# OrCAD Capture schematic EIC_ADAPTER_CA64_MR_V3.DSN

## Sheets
1 PAGE1-BIS: size A3; title: EIC-Adapter_Carrier-ALCOR 64; rev: 3; note: Connections
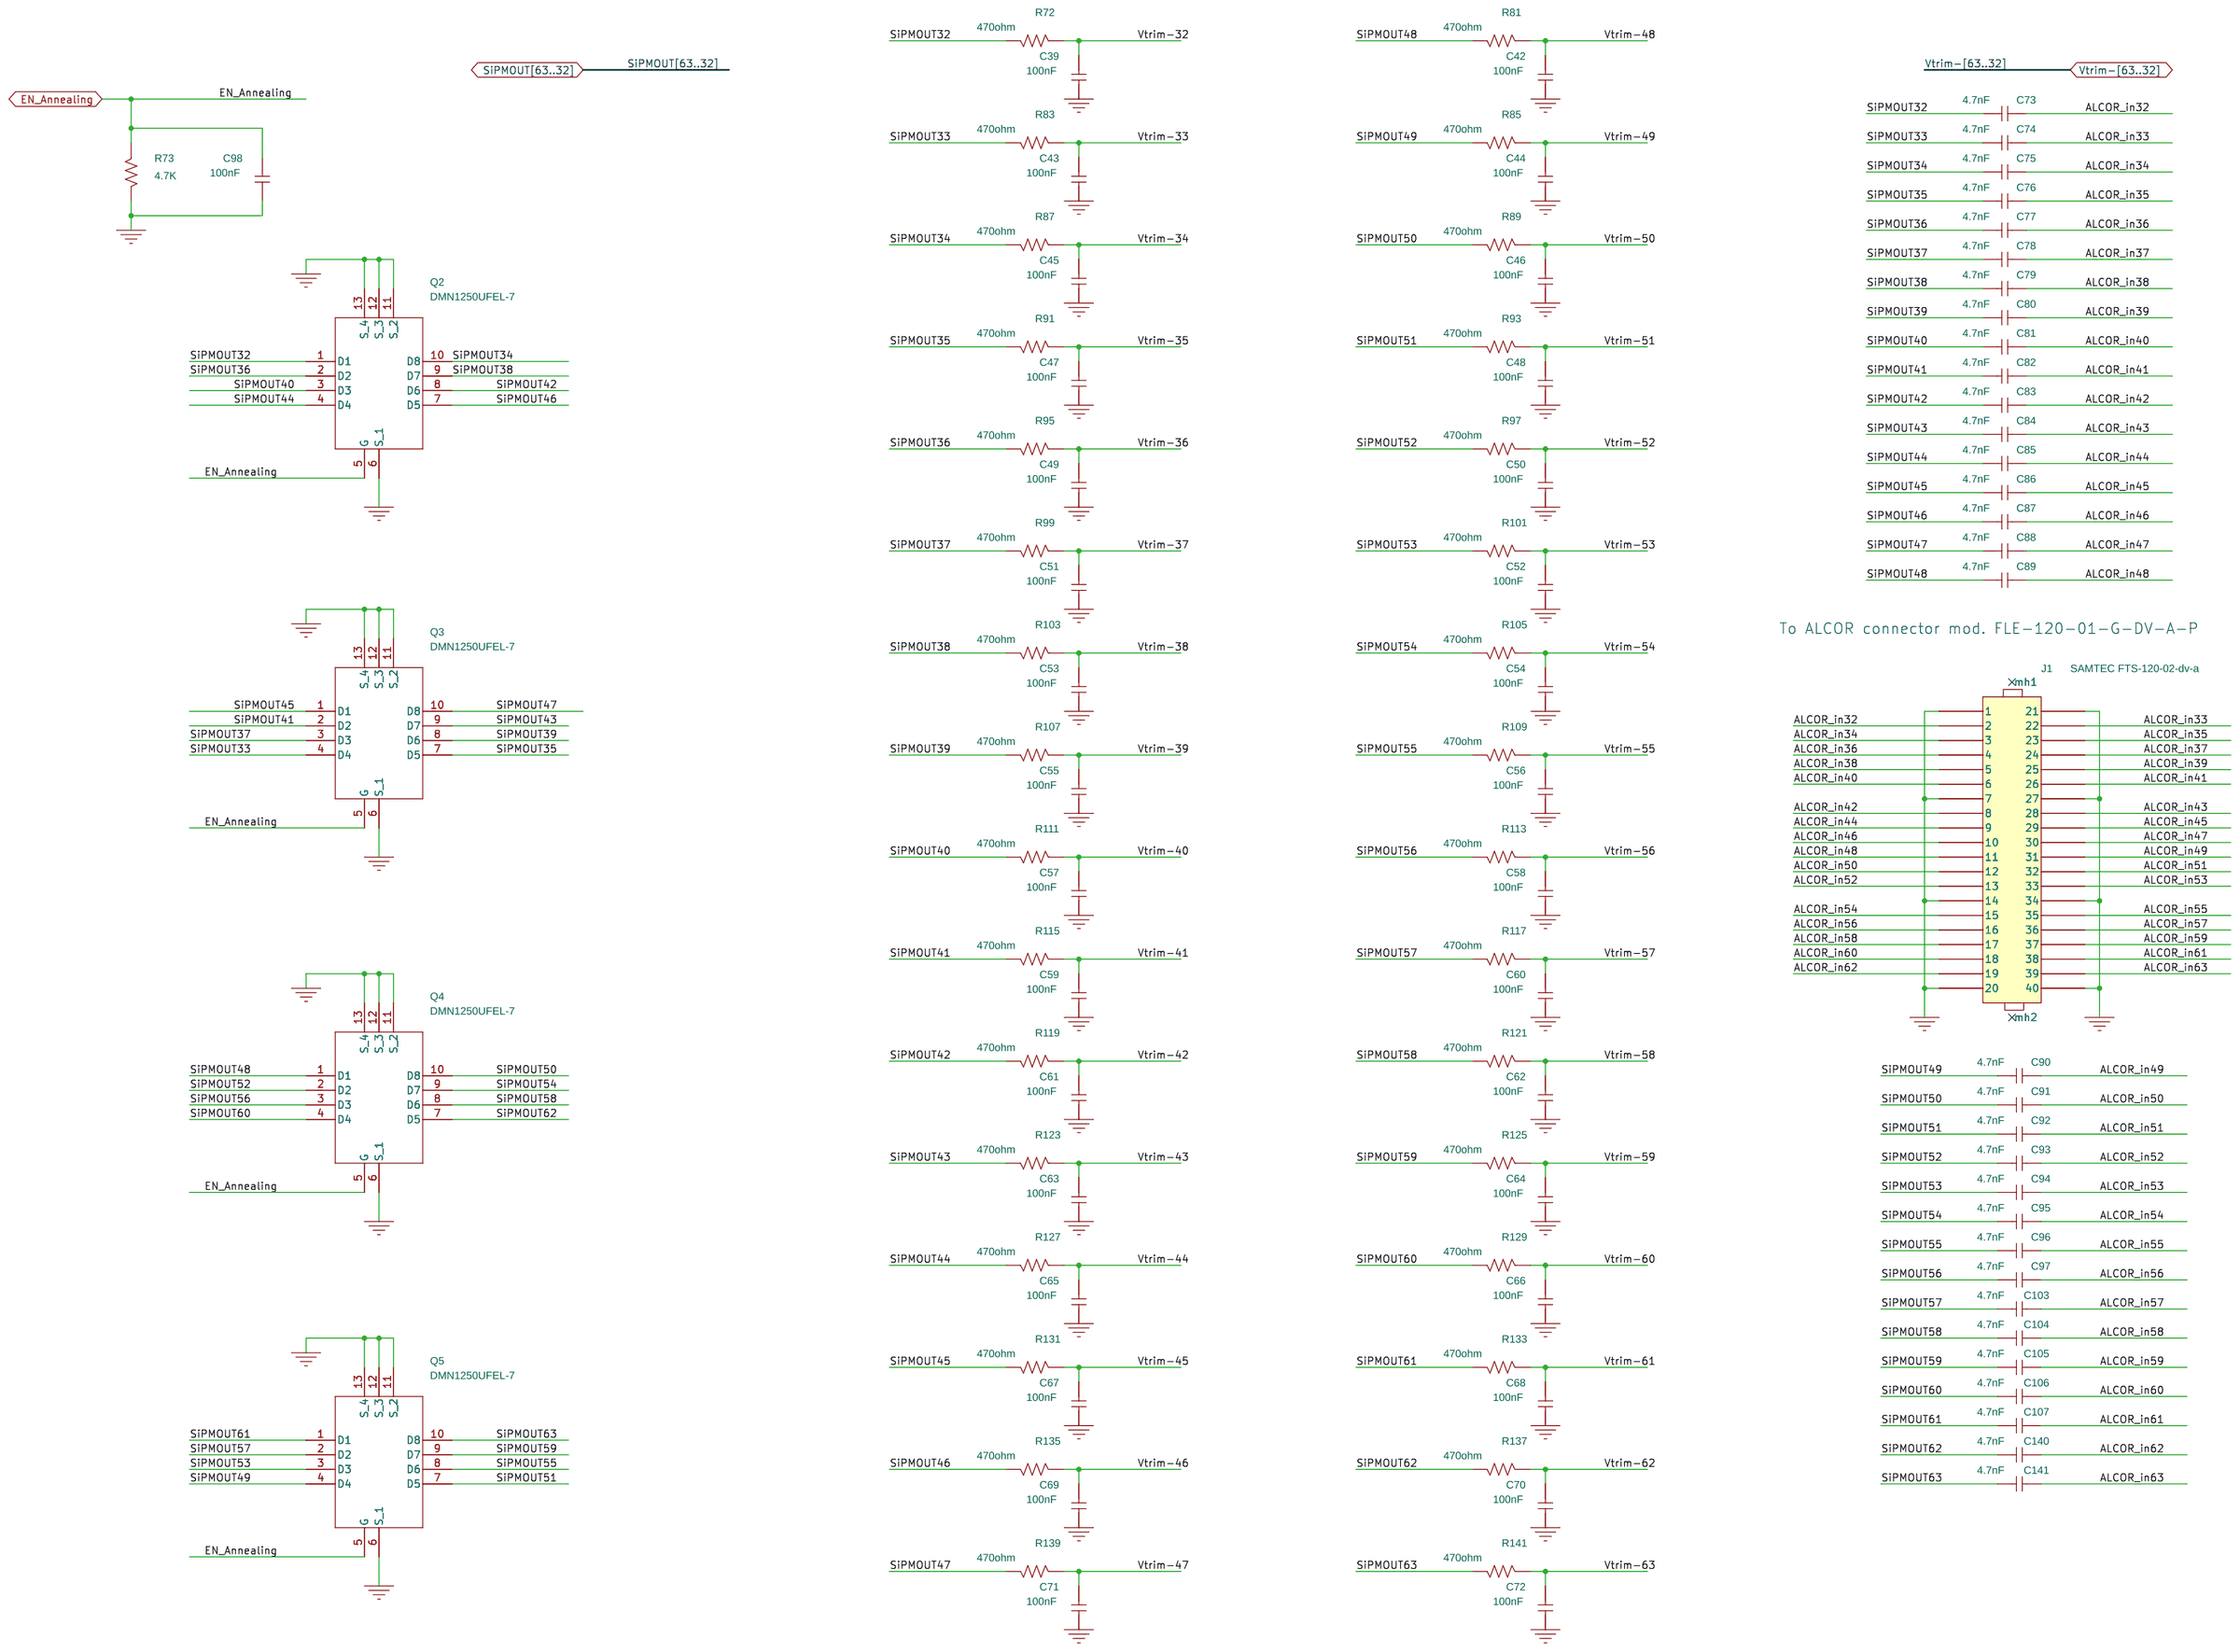
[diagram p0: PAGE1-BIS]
2 Note: note: note
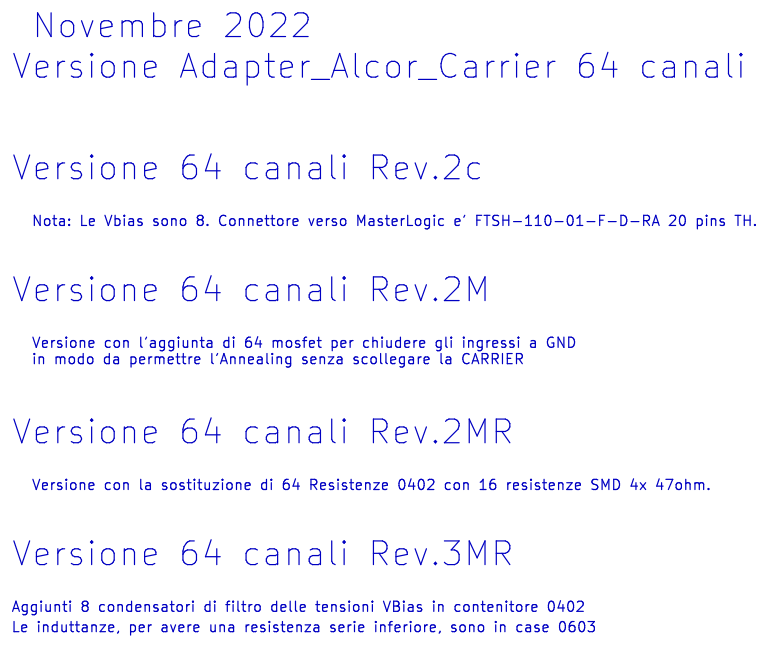
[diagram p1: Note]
3 PAGE2: size A3; note: Trim-DACs
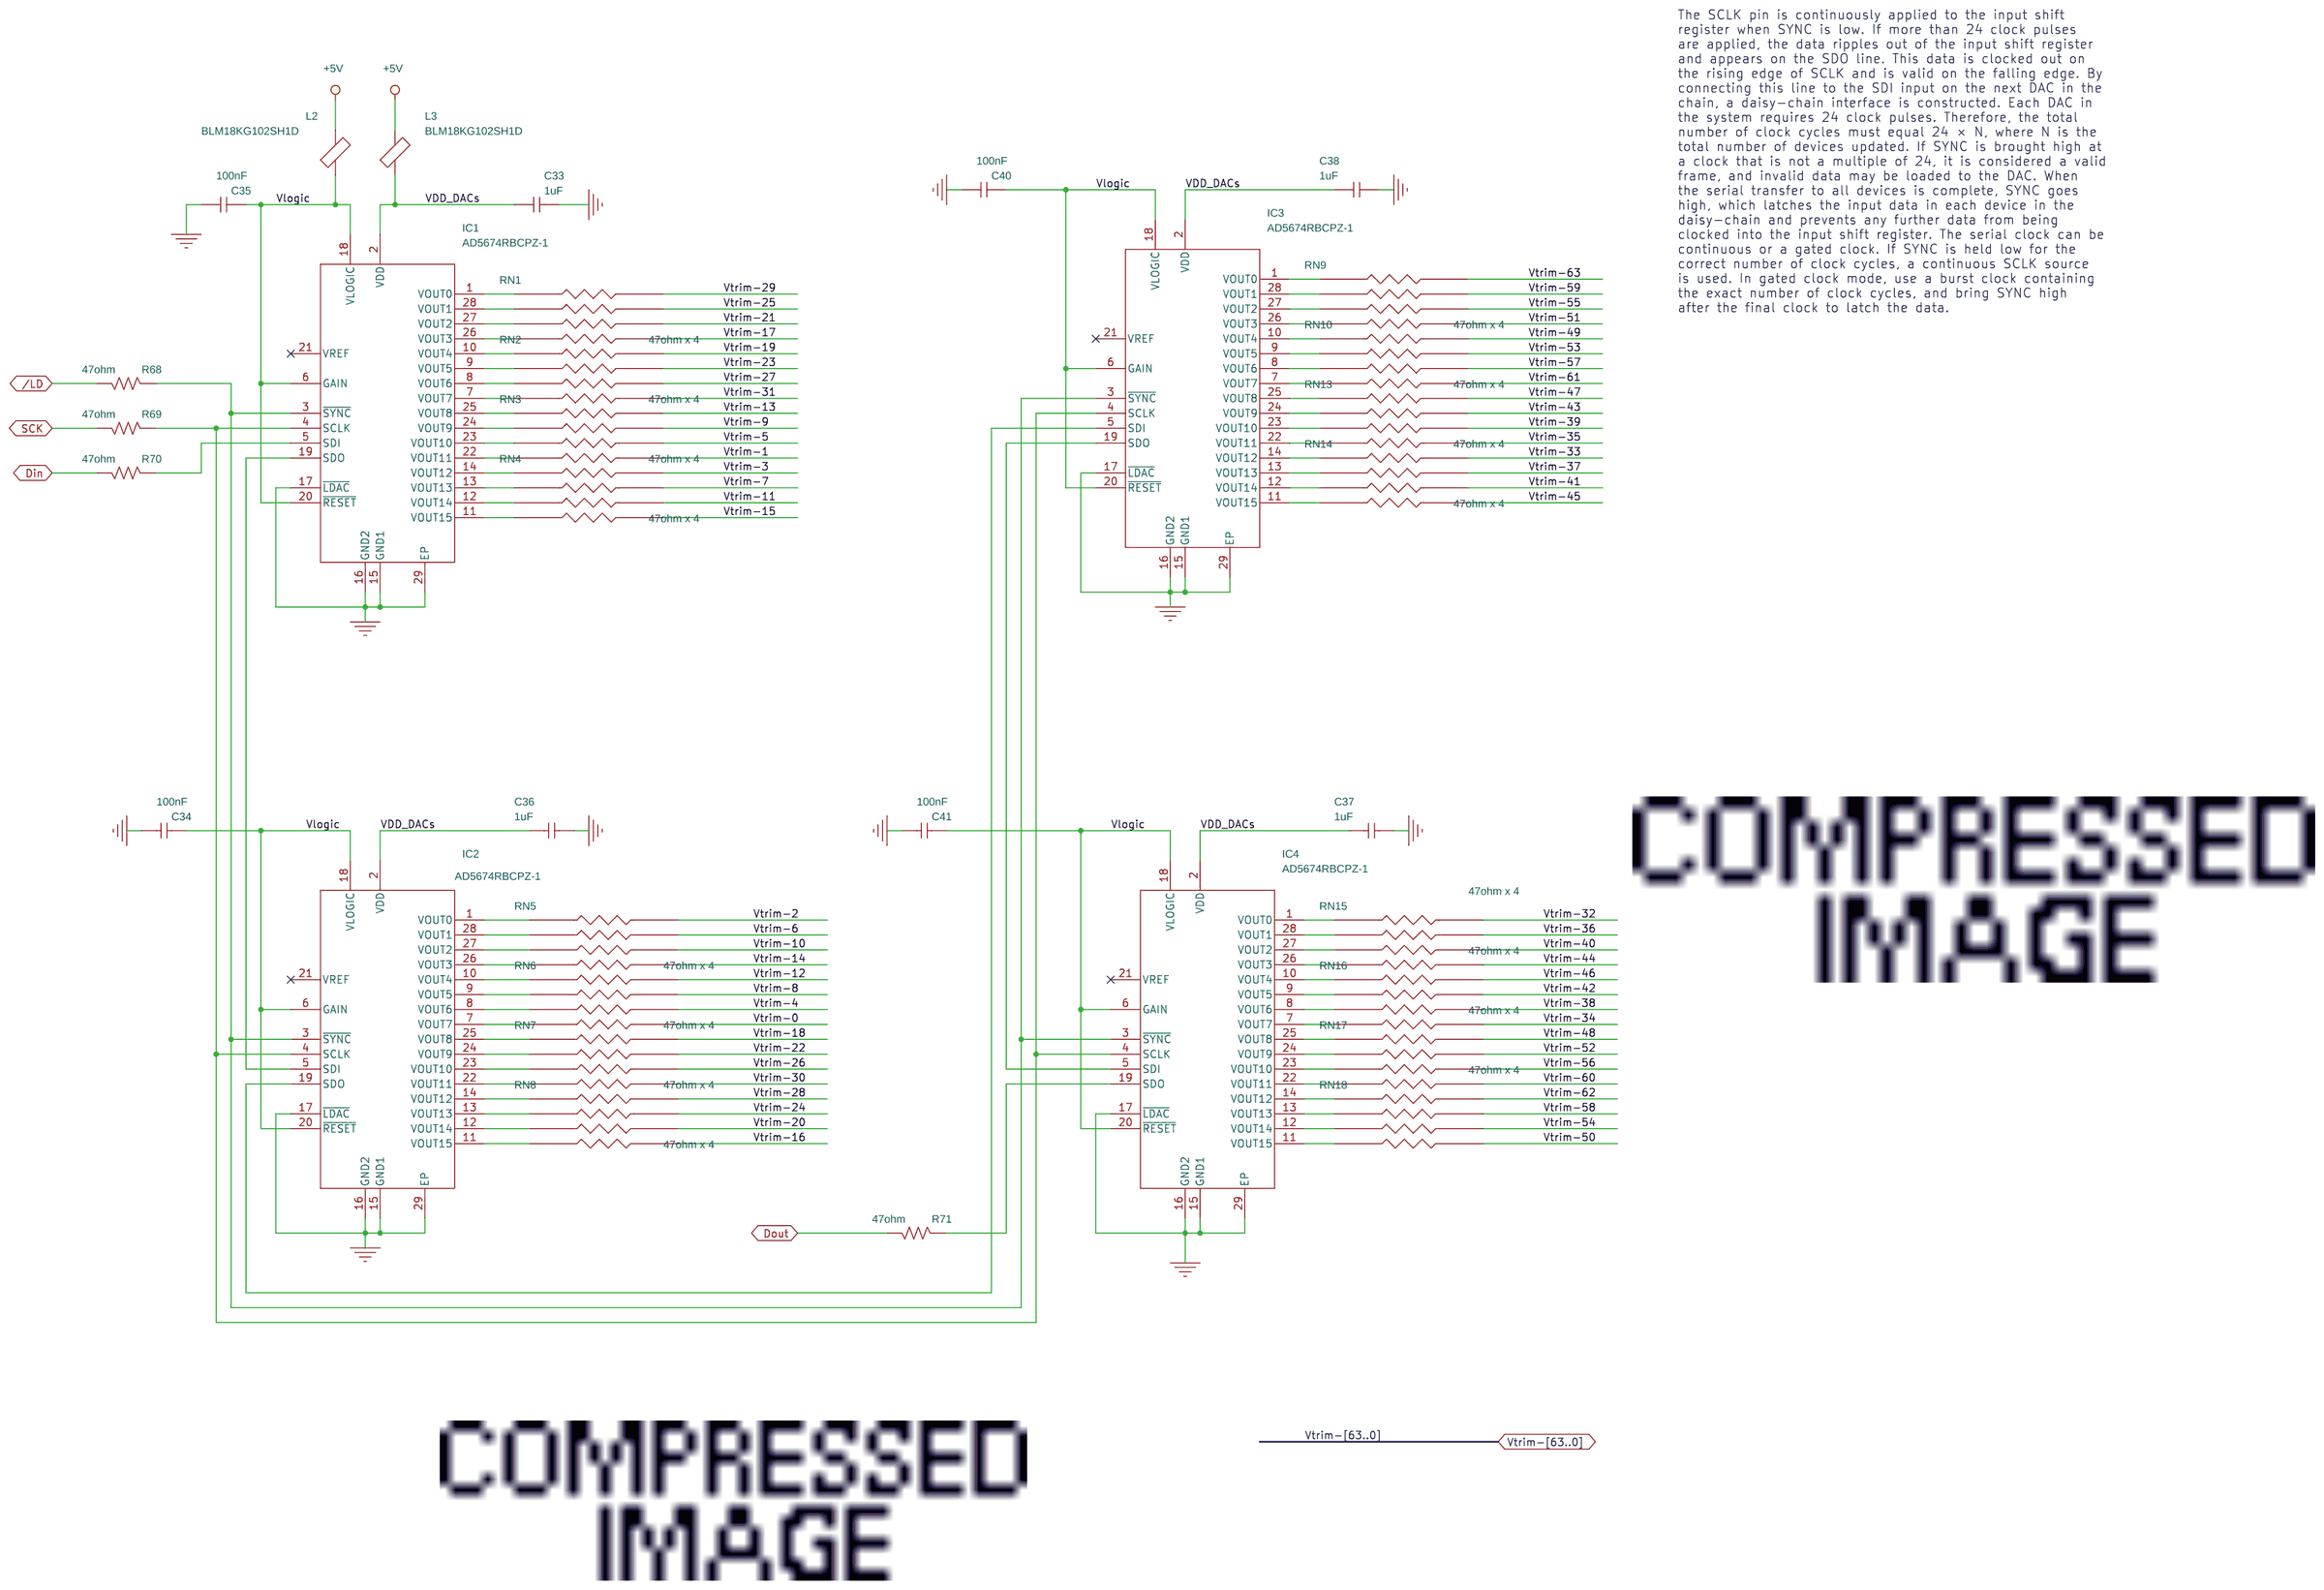
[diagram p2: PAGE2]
4 PAGE1: size A3
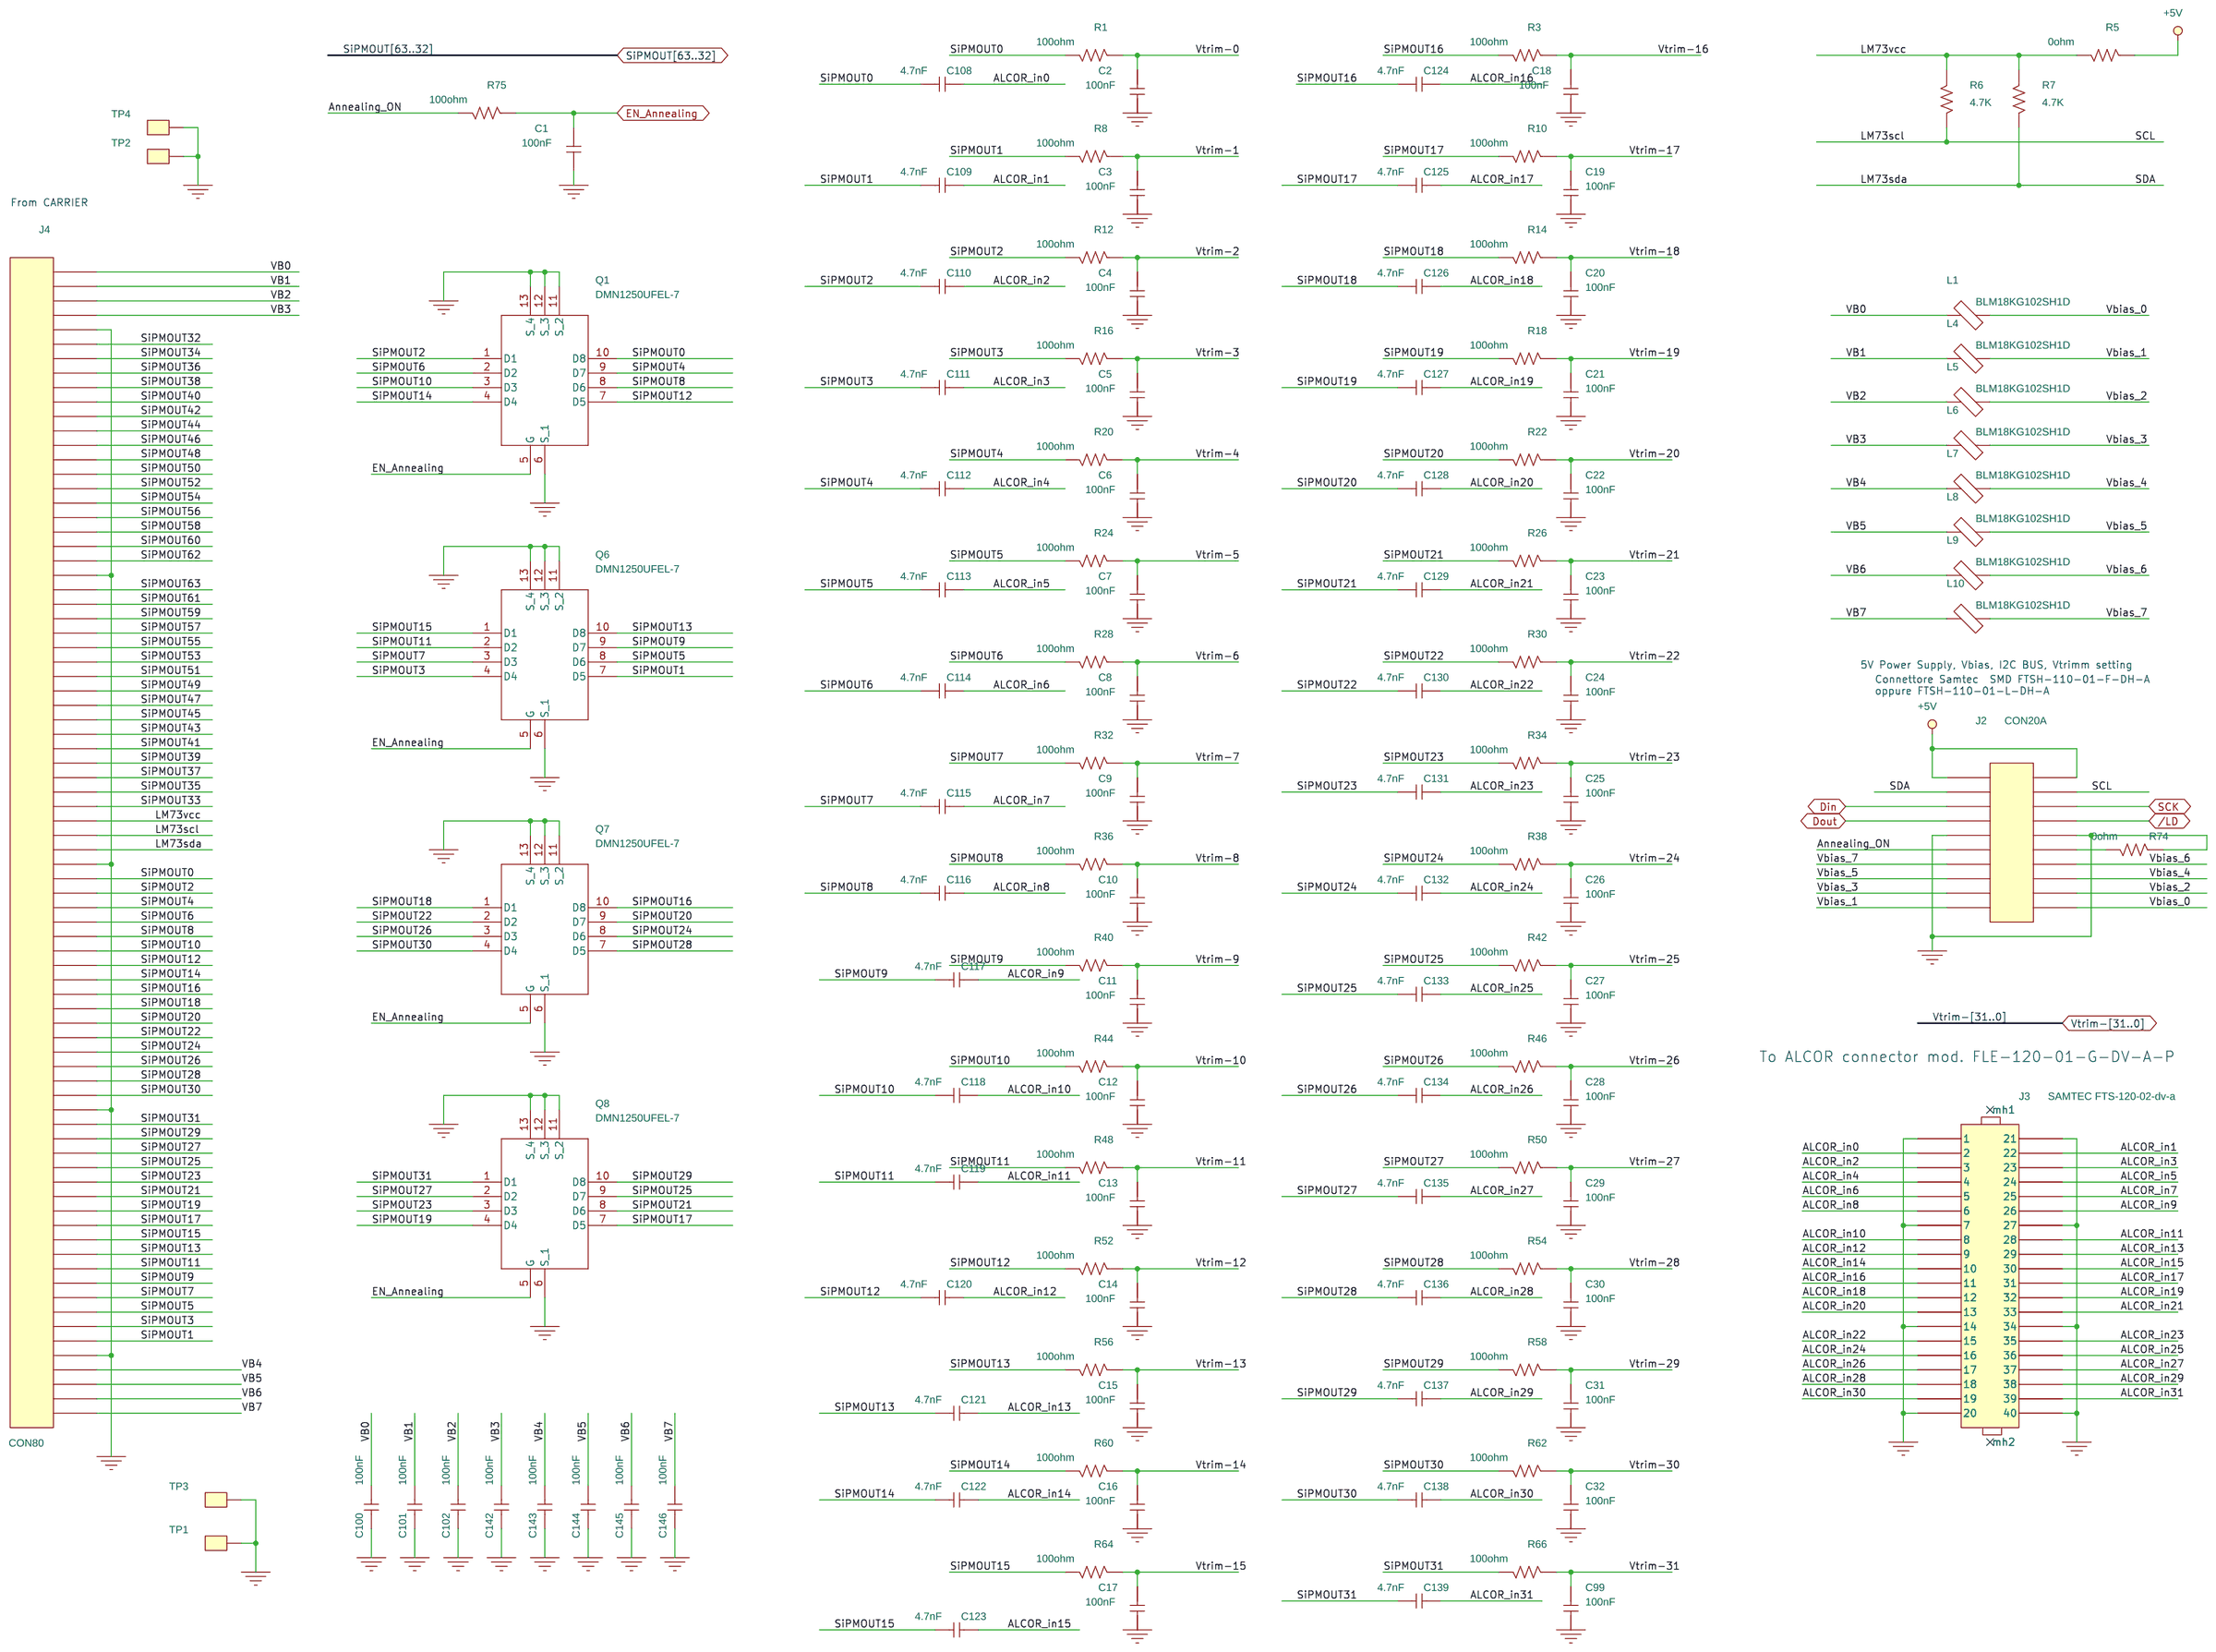
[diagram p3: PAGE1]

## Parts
sheet PAGE1-BIS
C39  100nF  [sm_c_0402_r]
C42  100nF  [sm_c_0402_r]
C43  100nF  [sm_c_0402_r]
C44  100nF  [sm_c_0402_r]
C45  100nF  [sm_c_0402_r]
C46  100nF  [sm_c_0402_r]
C47  100nF  [sm_c_0402_r]
C48  100nF  [sm_c_0402_r]
C49  100nF  [sm_c_0402_r]
C50  100nF  [sm_c_0402_r]
C51  100nF  [sm_c_0402_r]
C52  100nF  [sm_c_0402_r]
C53  100nF  [sm_c_0402_r]
C54  100nF  [sm_c_0402_r]
C55  100nF  [sm_c_0402_r]
C56  100nF  [sm_c_0402_r]
C57  100nF  [sm_c_0402_r]
C58  100nF  [sm_c_0402_r]
C59  100nF  [sm_c_0402_r]
C60  100nF  [sm_c_0402_r]
C61  100nF  [sm_c_0402_r]
C62  100nF  [sm_c_0402_r]
C63  100nF  [sm_c_0402_r]
C64  100nF  [sm_c_0402_r]
C65  100nF  [sm_c_0402_r]
C66  100nF  [sm_c_0402_r]
C67  100nF  [sm_c_0402_r]
C68  100nF  [sm_c_0402_r]
C69  100nF  [sm_c_0402_r]
C70  100nF  [sm_c_0402_r]
C71  100nF  [sm_c_0402_r]
C72  100nF  [sm_c_0402_r]
C73  4.7nF  [SM_C_0402_r]
C74  4.7nF  [SM_C_0402_r]
C75  4.7nF  [SM_C_0402_r]
C76  4.7nF  [SM_C_0402_r]
C77  4.7nF  [SM_C_0402_r]
C78  4.7nF  [SM_C_0402_r]
C79  4.7nF  [SM_C_0402_r]
C80  4.7nF  [SM_C_0402_r]
C81  4.7nF  [SM_C_0402_r]
C82  4.7nF  [SM_C_0402_r]
C83  4.7nF  [SM_C_0402_r]
C84  4.7nF  [SM_C_0402_r]
C85  4.7nF  [SM_C_0402_r]
C86  4.7nF  [SM_C_0402_r]
C87  4.7nF  [SM_C_0402_r]
C88  4.7nF  [SM_C_0402_r]
C89  4.7nF  [SM_C_0402_r]
C90  4.7nF  [SM_C_0402_r]
C91  4.7nF  [SM_C_0402_r]
C92  4.7nF  [SM_C_0402_r]
C93  4.7nF  [SM_C_0402_r]
C94  4.7nF  [SM_C_0402_r]
C95  4.7nF  [SM_C_0402_r]
C96  4.7nF  [SM_C_0402_r]
C97  4.7nF  [SM_C_0402_r]
C98  100nF  [sm_c_0402_r]
C103  4.7nF  [SM_C_0402_r]
C104  4.7nF  [SM_C_0402_r]
C105  4.7nF  [SM_C_0402_r]
C106  4.7nF  [SM_C_0402_r]
C107  4.7nF  [SM_C_0402_r]
C140  4.7nF  [SM_C_0402_r]
C141  4.7nF  [SM_C_0402_r]
J1  SAMTEC FTS-120-02-dv-a  [fts-120-x-dv-a]
Q2  DMN1250UFEL-7  [QFN13P1_50X1_50]
Q3  DMN1250UFEL-7  [QFN13P1_50X1_50]
Q4  DMN1250UFEL-7  [QFN13P1_50X1_50]
Q5  DMN1250UFEL-7  [QFN13P1_50X1_50]
R72  470ohm  [sm_r_0402_r]
R73  4.7K  [sm_r_0402_r]
R81  470ohm  [sm_r_0402_r]
R83  470ohm  [sm_r_0402_r]
R85  470ohm  [sm_r_0402_r]
R87  470ohm  [sm_r_0402_r]
R89  470ohm  [sm_r_0402_r]
R91  470ohm  [sm_r_0402_r]
R93  470ohm  [sm_r_0402_r]
R95  470ohm  [sm_r_0402_r]
R97  470ohm  [sm_r_0402_r]
R99  470ohm  [sm_r_0402_r]
R101  470ohm  [sm_r_0402_r]
R103  470ohm  [sm_r_0402_r]
R105  470ohm  [sm_r_0402_r]
R107  470ohm  [sm_r_0402_r]
R109  470ohm  [sm_r_0402_r]
R111  470ohm  [sm_r_0402_r]
R113  470ohm  [sm_r_0402_r]
R115  470ohm  [sm_r_0402_r]
R117  470ohm  [sm_r_0402_r]
R119  470ohm  [sm_r_0402_r]
R121  470ohm  [sm_r_0402_r]
R123  470ohm  [sm_r_0402_r]
R125  470ohm  [sm_r_0402_r]
R127  470ohm  [sm_r_0402_r]
R129  470ohm  [sm_r_0402_r]
R131  470ohm  [sm_r_0402_r]
R133  470ohm  [sm_r_0402_r]
R135  470ohm  [sm_r_0402_r]
R137  470ohm  [sm_r_0402_r]
R139  470ohm  [sm_r_0402_r]
R141  470ohm  [sm_r_0402_r]
sheet PAGE1
C1  100nF  [sm_c_0402_r]
C2  100nF  [sm_c_0402_r]
C3  100nF  [sm_c_0402_r]
C4  100nF  [sm_c_0402_r]
C5  100nF  [sm_c_0402_r]
C6  100nF  [sm_c_0402_r]
C7  100nF  [sm_c_0402_r]
C8  100nF  [sm_c_0402_r]
C9  100nF  [sm_c_0402_r]
C10  100nF  [sm_c_0402_r]
C11  100nF  [sm_c_0402_r]
C12  100nF  [sm_c_0402_r]
C13  100nF  [sm_c_0402_r]
C14  100nF  [sm_c_0402_r]
C15  100nF  [sm_c_0402_r]
C16  100nF  [sm_c_0402_r]
C17  100nF  [sm_c_0402_r]
C18  100nF  [sm_c_0402_r]
C19  100nF  [sm_c_0402_r]
C20  100nF  [sm_c_0402_r]
C21  100nF  [sm_c_0402_r]
C22  100nF  [sm_c_0402_r]
C23  100nF  [sm_c_0402_r]
C24  100nF  [sm_c_0402_r]
C25  100nF  [sm_c_0402_r]
C26  100nF  [sm_c_0402_r]
C27  100nF  [sm_c_0402_r]
C28  100nF  [sm_c_0402_r]
C29  100nF  [sm_c_0402_r]
C30  100nF  [sm_c_0402_r]
C31  100nF  [sm_c_0402_r]
C32  100nF  [sm_c_0402_r]
C99  100nF  [sm_c_0402_r]
C100  100nF  [sm_c_0402_r]
C101  100nF  [sm_c_0402_r]
C102  100nF  [sm_c_0402_r]
C108  4.7nF  [SM_C_0402_r]
C109  4.7nF  [SM_C_0402_r]
C110  4.7nF  [SM_C_0402_r]
C111  4.7nF  [SM_C_0402_r]
C112  4.7nF  [SM_C_0402_r]
C113  4.7nF  [SM_C_0402_r]
C114  4.7nF  [SM_C_0402_r]
C115  4.7nF  [SM_C_0402_r]
C116  4.7nF  [SM_C_0402_r]
C117  4.7nF  [SM_C_0402_r]
C118  4.7nF  [SM_C_0402_r]
C119  4.7nF  [SM_C_0402_r]
C120  4.7nF  [SM_C_0402_r]
C121  4.7nF  [SM_C_0402_r]
C122  4.7nF  [SM_C_0402_r]
C123  4.7nF  [SM_C_0402_r]
C124  4.7nF  [SM_C_0402_r]
C125  4.7nF  [SM_C_0402_r]
C126  4.7nF  [SM_C_0402_r]
C127  4.7nF  [SM_C_0402_r]
C128  4.7nF  [SM_C_0402_r]
C129  4.7nF  [SM_C_0402_r]
C130  4.7nF  [SM_C_0402_r]
C131  4.7nF  [SM_C_0402_r]
C132  4.7nF  [SM_C_0402_r]
C133  4.7nF  [SM_C_0402_r]
C134  4.7nF  [SM_C_0402_r]
C135  4.7nF  [SM_C_0402_r]
C136  4.7nF  [SM_C_0402_r]
C137  4.7nF  [SM_C_0402_r]
C138  4.7nF  [SM_C_0402_r]
C139  4.7nF  [SM_C_0402_r]
C142  100nF  [sm_c_0402_r]
C143  100nF  [sm_c_0402_r]
C144  100nF  [sm_c_0402_r]
C145  100nF  [sm_c_0402_r]
C146  100nF  [sm_c_0402_r]
J2  CON20A  [SAMTEC_FTSH-110-01-F-DH-A]
J3  SAMTEC FTS-120-02-dv-a  [fts-120-x-dv-a]
J4  CON80  [Conn_HIROSE_FH30-80S-04]
L1  BLM18KG102SH1D  [sm_l_0603_r]
L4  BLM18KG102SH1D  [sm_l_0603_r]
L5  BLM18KG102SH1D  [sm_l_0603_r]
L6  BLM18KG102SH1D  [sm_l_0603_r]
L7  BLM18KG102SH1D  [sm_l_0603_r]
L8  BLM18KG102SH1D  [sm_l_0603_r]
L9  BLM18KG102SH1D  [sm_l_0603_r]
L10  BLM18KG102SH1D  [sm_l_0603_r]
Q1  DMN1250UFEL-7  [QFN13P1_50X1_50]
Q6  DMN1250UFEL-7  [QFN13P1_50X1_50]
Q7  DMN1250UFEL-7  [QFN13P1_50X1_50]
Q8  DMN1250UFEL-7  [QFN13P1_50X1_50]
R1  100ohm  [sm_r_0402_r]
R3  100ohm  [sm_r_0402_r]
R5  0ohm  [sm_r_0402_r]
R6  4.7K  [sm_R_0402]
R7  4.7K  [sm_R_0402]
R8  100ohm  [sm_r_0402_r]
R10  100ohm  [sm_r_0402_r]
R12  100ohm  [sm_r_0402_r]
R14  100ohm  [sm_r_0402_r]
R16  100ohm  [sm_r_0402_r]
R18  100ohm  [sm_r_0402_r]
R20  100ohm  [sm_r_0402_r]
R22  100ohm  [sm_r_0402_r]
R24  100ohm  [sm_r_0402_r]
R26  100ohm  [sm_r_0402_r]
R28  100ohm  [sm_r_0402_r]
R30  100ohm  [sm_r_0402_r]
R32  100ohm  [sm_r_0402_r]
R34  100ohm  [sm_r_0402_r]
R36  100ohm  [sm_r_0402_r]
R38  100ohm  [sm_r_0402_r]
R40  100ohm  [sm_r_0402_r]
R42  100ohm  [sm_r_0402_r]
R44  100ohm  [sm_r_0402_r]
R46  100ohm  [sm_r_0402_r]
R48  100ohm  [sm_r_0402_r]
R50  100ohm  [sm_r_0402_r]
R52  100ohm  [sm_r_0402_r]
R54  100ohm  [sm_r_0402_r]
R56  100ohm  [sm_r_0402_r]
R58  100ohm  [sm_r_0402_r]
R60  100ohm  [sm_r_0402_r]
R62  100ohm  [sm_r_0402_r]
R64  100ohm  [sm_r_0402_r]
R66  100ohm  [sm_r_0402_r]
R74  0ohm  [sm_R_0402_r]
R75  100ohm  [sm_r_0402_r]
TP1  TP  [pin]
TP2  TP  [pin]
TP3  TP  [pin]
TP4  TP  [pin]
sheet PAGE2
C33  1uF  [sm_c_0603]
C34  100nF  [sm_c_0402_r]
C35  100nF  [sm_c_0402_r]
C36  1uF  [sm_c_0603]
C37  1uF  [sm_c_0603]
C38  1uF  [sm_c_0603]
C40  100nF  [sm_c_0402_r]
C41  100nF  [sm_c_0402_r]
IC1  AD5674RBCPZ-1  [QFN29P4X4X]
IC2  AD5674RBCPZ-1  [QFN29P4X4X]
IC3  AD5674RBCPZ-1  [QFN29P4X4X]
IC4  AD5674RBCPZ-1  [QFN29P4X4X]
L2  BLM18KG102SH1D  [SM_L_0603_r]
L3  BLM18KG102SH1D  [SM_L_0603_r]
R68  47ohm  [sm_r_0402_r]
R69  47ohm  [sm_r_0402_r]
R70  47ohm  [sm_r_0402_r]
R71  47ohm  [sm_r_0402_r]
RN1  47ohm x 4  [array_CAY10-J4_8p]
RN2  47ohm x 4  [array_CAY10-J4_8p]
RN3  47ohm x 4  [array_CAY10-J4_8p]
RN4  47ohm x 4  [array_CAY10-J4_8p]
RN5  47ohm x 4  [array_CAY10-J4_8p]
RN6  47ohm x 4  [array_CAY10-J4_8p]
RN7  47ohm x 4  [array_CAY10-J4_8p]
RN8  47ohm x 4  [array_CAY10-J4_8p]
RN9  47ohm x 4  [array_CAY10-J4_8p]
RN10  47ohm x 4  [array_CAY10-J4_8p]
RN13  47ohm x 4  [array_CAY10-J4_8p]
RN14  47ohm x 4  [array_CAY10-J4_8p]
RN15  47ohm x 4  [array_CAY10-J4_8p]
RN16  47ohm x 4  [array_CAY10-J4_8p]
RN17  47ohm x 4  [array_CAY10-J4_8p]
RN18  47ohm x 4  [array_CAY10-J4_8p]

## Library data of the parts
C1-C32 C34 C35 C39-C72 C98 C99 = C-100nF: Manufacturer: TDK; Part Code: CGA2B3X7R1E104K050BB; Vendor Code: 810-CGA2B3X7R1E104K
C73-C97 C103-C107 C109-C141 = C: Manufacturer: Taiyo Yuden; Part Code: HMK105B7472KV-F; Vendor Code: 963-HMK105B7472KV-F
J1 J3 = FTSH-120-03-F-DV: Manufacturer: SAMTEC; Part Code: FTS-120-02-L-DV; Vendor Code: ADELSY
Q1-Q8 = DMN1250UFEL-7: 3D_Image_URL: https://componentsearchengine.com/2D/0T/2292974.1.1.png; Body_Length: 1.55; Body_Width: 1.55; Category: MOSFET (N-Channel); Confidence: C3 - Community checked; Height: 0.63; Manufacturer: Diodes Inc.; Package_Category: Quad Flat No-Lead; Pin_Count: 13; Released_Date: 2020-08-11 05:17:30; Source_Version: 1.1; Status: Released; Vendor Code: 621-DMN1250UFEL-7
R1 R3 R5-R8 R10 R12 R14 R16 R18 R20 R22 R24 R26 R28 R30 R32 R34 R36 R38 R40 R42 R44 R46 R48 R50 R52 R54 R56 R58 R60 R62 R64 R66 R68-R75 R81 R83 R85 R87 R89 R91 R93 R95 R97 R99 R101 R103 R105 R107 R109 R111 R113 R115 R117 R119 R121 R123 R125 R127 R129 R131 R133 R135 R137 R139 R141 = R
C100-C102 C142-C146 = C-100nF: Manufacturer: Murata; Part Code: GRM155R62A104KE14J; Vendor Code: 81-GRM155R62A104KE4J
C108 = C: Manufacturer: Taiyo Yuden; Part Code: 963-HMK105B7472KV-F; Vendor Code: 963-HMK105B7472KV-F
J2 = CON20A: Manufacturer: SAMTEC; Part Code: FTSH-110-01-L-DH-A; Vendor Code: 200-FTSH11001LDHA
J4 = CON80: Manufacturer: HIROSE; Part Code: FH30M-80S-0.4SHW(05); Vendor Code: 798-FH30M80S04SHW05
L1-L10 = BEAD_SM0603: Vendor Code: 81-BLM18KG102SH1D
TP1-TP4 = TP
C33 C36-C38 = C-100nF: Manufacturer: TDK; Part Code: CGA3E1X7R1V105K080AC; Vendor Code: 810-CGA3E1X7R1V105KC
IC1-IC4 = AD5674RBCPZ: 3D_Image_URL: https://componentsearchengine.com/2D/0T/10462103.2.1.png; Body_Length: 4.1; Body_Width: 4.1; Category: Integrated Circuit; Confidence: C3 - Community checked; Height: 1; Manufacturer: Analog Devices; Package_Category: Quad Flat No-Lead; Pin_Count: 29; Released_Date: 2020-06-25 13:35:10; Source_Version: 2.1; Status: Released
RN1-RN10 RN13-RN18 = RES_ISO8: Manufacturer: BOURNS; Part Code: CAY10A-470J4LF; Vendor Code: 652-CAY10A-470J4LF

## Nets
+5V: J2.1 J2.2 L2.2 L3.2 R5.1
VDD_DACs: C33.2 C36.2 C37.2 C38.2 IC1.2(VDD) IC2.2(VDD) IC3.2(VDD) IC4.2(VDD) L3.1
0: C1.1 C2.1 C3.1 C4.1 C5.1 C6.1 C7.1 C8.1 C9.1 C10.1 C11.1 C12.1 C13.1 C14.1 C15.1 C16.1 C17.1 C18.1 C19.1 C20.1 C21.1 C22.1 C23.1 C24.1 C25.1 C26.1 C27.1 C28.1 C29.1 C30.1 C31.1 C32.1 C33.1 C34.1 C35.1 C36.1 C37.1 C38.1 C39.1 C40.1 C41.1 C42.1 C43.1 C44.1 C45.1 C46.1 C47.1 C48.1 C49.1 C50.1 C51.1 C52.1 C53.1 C54.1 C55.1 C56.1 C57.1 C58.1 C59.1 C60.1 C61.1 C62.1 C63.1 C64.1 C65.1 C66.1 C67.1 C68.1 C69.1 C70.1 C71.1 C72.1 C98.1 C99.1 C100.1 C101.1 C102.1 C142.1 C143.1 C144.1 C145.1 C146.1 IC1.15(GND1) IC1.16(GND2) IC1.17(~{LDAC}) IC1.29(EP) IC2.15(GND1) IC2.16(GND2) IC2.17(~{LDAC}) IC2.29(EP) IC3.15(GND1) IC3.16(GND2) IC3.17(~{LDAC}) IC3.29(EP) IC4.15(GND1) IC4.16(GND2) IC4.17(~{LDAC}) IC4.29(EP) J1.1(21) J1.2(1) J1.13(27) J1.14(7) J1.27(34) J1.28(14) J1.39(40) J1.40(20) J2.9 J2.10 J3.1(21) J3.2(1) J3.13(27) J3.14(7) J3.27(34) J3.28(14) J3.39(40) J3.40(20) J4.5 J4.22 J4.42 J4.59 J4.76 Q1.6(S_1) Q1.11(S_2) Q1.12(S_3) Q1.13(S_4) Q2.6(S_1) Q2.11(S_2) Q2.12(S_3) Q2.13(S_4) Q3.6(S_1) Q3.11(S_2) Q3.12(S_3) Q3.13(S_4) Q4.6(S_1) Q4.11(S_2) Q4.12(S_3) Q4.13(S_4) Q5.6(S_1) Q5.11(S_2) Q5.12(S_3) Q5.13(S_4) Q6.6(S_1) Q6.11(S_2) Q6.12(S_3) Q6.13(S_4) Q7.6(S_1) Q7.11(S_2) Q7.12(S_3) Q7.13(S_4) Q8.6(S_1) Q8.11(S_2) Q8.12(S_3) Q8.13(S_4) R73.2 R74.1 TP1.1 TP2.1 TP3.1 TP4.1
/LD: J2.8 R68.2
ALCOR_in0: C108.1 J3.4(2)
ALCOR_in1: C109.1 J3.3(22)
ALCOR_in2: C110.1 J3.6(3)
ALCOR_in3: C111.1 J3.5(23)
ALCOR_in4: C112.1 J3.8(4)
ALCOR_in5: C113.1 J3.7(24)
ALCOR_in6: C114.1 J3.10(5)
ALCOR_in7: C115.1 J3.9(25)
ALCOR_in8: C116.1 J3.12(6)
ALCOR_in9: C117.1 J3.11(26)
ALCOR_in10: C118.1 J3.16(8)
ALCOR_in11: C119.1 J3.15(28)
ALCOR_in12: C120.1 J3.18(9)
ALCOR_in13: C121.1 J3.17(29)
ALCOR_in14: C122.1 J3.20(10)
ALCOR_in15: C123.1 J3.19(30)
ALCOR_in16: C124.1 J3.22(11)
ALCOR_in17: C125.1 J3.21(31)
ALCOR_in18: C126.1 J3.24(12)
ALCOR_in19: C127.1 J3.23(32)
ALCOR_in20: C128.1 J3.26(13)
ALCOR_in21: C129.1 J3.25(33)
ALCOR_in22: C130.1 J3.30(15)
ALCOR_in23: C131.1 J3.29(35)
ALCOR_in24: C132.1 J3.32(16)
ALCOR_in25: C133.1 J3.31(36)
ALCOR_in26: C134.1 J3.34(17)
ALCOR_in27: C135.1 J3.33(37)
ALCOR_in28: C136.1 J3.36(18)
ALCOR_in29: C137.1 J3.35(38)
ALCOR_in30: C138.1 J3.38(19)
ALCOR_in31: C139.1 J3.37(39)
ALCOR_in32: C73.1 J1.4(2)
ALCOR_in33: C74.1 J1.3(22)
ALCOR_in34: C75.1 J1.6(3)
ALCOR_in35: C76.1 J1.5(23)
ALCOR_in36: C77.1 J1.8(4)
ALCOR_in37: C78.1 J1.7(24)
ALCOR_in38: C79.1 J1.10(5)
ALCOR_in39: C80.1 J1.9(25)
ALCOR_in40: C81.1 J1.12(6)
ALCOR_in41: C82.1 J1.11(26)
ALCOR_in42: C83.1 J1.16(8)
ALCOR_in43: C84.1 J1.15(28)
ALCOR_in44: C85.1 J1.18(9)
ALCOR_in45: C86.1 J1.17(29)
ALCOR_in46: C87.1 J1.20(10)
ALCOR_in47: C88.1 J1.19(30)
ALCOR_in48: C89.1 J1.22(11)
ALCOR_in49: C90.1 J1.21(31)
ALCOR_in50: C91.1 J1.24(12)
ALCOR_in51: C92.1 J1.23(32)
ALCOR_in52: C93.1 J1.26(13)
ALCOR_in53: C94.1 J1.25(33)
ALCOR_in54: C95.1 J1.30(15)
ALCOR_in55: C96.1 J1.29(35)
ALCOR_in56: C97.1 J1.32(16)
ALCOR_in57: C103.1 J1.31(36)
ALCOR_in58: C104.1 J1.34(17)
ALCOR_in59: C105.1 J1.33(37)
ALCOR_in60: C106.1 J1.36(18)
ALCOR_in61: C107.1 J1.35(38)
ALCOR_in62: C140.1 J1.38(19)
ALCOR_in63: C141.1 J1.37(39)
Annealing_ON: J2.11 R75.2
Din: J2.5 R70.2
Dout: J2.7 R71.2
EN_Annealing: C1.2 C98.2 Q1.5(G) Q2.5(G) Q3.5(G) Q4.5(G) Q5.5(G) Q6.5(G) Q7.5(G) Q8.5(G) R73.1 R75.1
LM73scl: J2.4 J4.40 R6.2
LM73sda: J2.3 J4.41 R7.2
LM73vcc: J4.39 R5.2 R6.1 R7.1
SCK: J2.6 R69.2
SiPMOUT0: C108.2 J4.43 Q1.10(D8) R1.2
SiPMOUT1: C109.2 J4.75 Q6.7(D5) R8.2
SiPMOUT2: C110.2 J4.44 Q1.1(D1) R12.2
SiPMOUT3: C111.2 J4.74 Q6.4(D4) R16.2
SiPMOUT4: C112.2 J4.45 Q1.9(D7) R20.2
SiPMOUT5: C113.2 J4.73 Q6.8(D6) R24.2
SiPMOUT6: C114.2 J4.46 Q1.2(D2) R28.2
SiPMOUT7: C115.2 J4.72 Q6.3(D3) R32.2
SiPMOUT8: C116.2 J4.47 Q1.8(D6) R36.2
SiPMOUT9: C117.2 J4.71 Q6.9(D7) R40.2
SiPMOUT10: C118.2 J4.48 Q1.3(D3) R44.2
SiPMOUT11: C119.2 J4.70 Q6.2(D2) R48.2
SiPMOUT12: C120.2 J4.49 Q1.7(D5) R52.2
SiPMOUT13: C121.2 J4.69 Q6.10(D8) R56.2
SiPMOUT14: C122.2 J4.50 Q1.4(D4) R60.2
SiPMOUT15: C123.2 J4.68 Q6.1(D1) R64.2
SiPMOUT16: C124.2 J4.51 Q7.10(D8) R3.2
SiPMOUT17: C125.2 J4.67 Q8.7(D5) R10.2
SiPMOUT18: C126.2 J4.52 Q7.1(D1) R14.2
SiPMOUT19: C127.2 J4.66 Q8.4(D4) R18.2
SiPMOUT20: C128.2 J4.53 Q7.9(D7) R22.2
SiPMOUT21: C129.2 J4.65 Q8.8(D6) R26.2
SiPMOUT22: C130.2 J4.54 Q7.2(D2) R30.2
SiPMOUT23: C131.2 J4.64 Q8.3(D3) R34.2
SiPMOUT24: C132.2 J4.55 Q7.8(D6) R38.2
SiPMOUT25: C133.2 J4.63 Q8.9(D7) R42.2
SiPMOUT26: C134.2 J4.56 Q7.3(D3) R46.2
SiPMOUT27: C135.2 J4.62 Q8.2(D2) R50.2
SiPMOUT28: C136.2 J4.57 Q7.7(D5) R54.2
SiPMOUT29: C137.2 J4.61 Q8.10(D8) R58.2
SiPMOUT30: C138.2 J4.58 Q7.4(D4) R62.2
SiPMOUT31: C139.2 J4.60 Q8.1(D1) R66.2
SiPMOUT32: C73.2 J4.6 Q2.1(D1) R72.2
SiPMOUT33: C74.2 J4.38 Q3.4(D4) R83.2
SiPMOUT34: C75.2 J4.7 Q2.10(D8) R87.2
SiPMOUT35: C76.2 J4.37 Q3.7(D5) R91.2
SiPMOUT36: C77.2 J4.8 Q2.2(D2) R95.2
SiPMOUT37: C78.2 J4.36 Q3.3(D3) R99.2
SiPMOUT38: C79.2 J4.9 Q2.9(D7) R103.2
SiPMOUT39: C80.2 J4.35 Q3.8(D6) R107.2
SiPMOUT40: C81.2 J4.10 Q2.3(D3) R111.2
SiPMOUT41: C82.2 J4.34 Q3.2(D2) R115.2
SiPMOUT42: C83.2 J4.11 Q2.8(D6) R119.2
SiPMOUT43: C84.2 J4.33 Q3.9(D7) R123.2
SiPMOUT44: C85.2 J4.12 Q2.4(D4) R127.2
SiPMOUT45: C86.2 J4.32 Q3.1(D1) R131.2
SiPMOUT46: C87.2 J4.13 Q2.7(D5) R135.2
SiPMOUT47: C88.2 J4.31 Q3.10(D8) R139.2
SiPMOUT48: C89.2 J4.14 Q4.1(D1) R81.2
SiPMOUT49: C90.2 J4.30 Q5.4(D4) R85.2
SiPMOUT50: C91.2 J4.15 Q4.10(D8) R89.2
SiPMOUT51: C92.2 J4.29 Q5.7(D5) R93.2
SiPMOUT52: C93.2 J4.16 Q4.2(D2) R97.2
SiPMOUT53: C94.2 J4.28 Q5.3(D3) R101.2
SiPMOUT54: C95.2 J4.17 Q4.9(D7) R105.2
SiPMOUT55: C96.2 J4.27 Q5.8(D6) R109.2
SiPMOUT56: C97.2 J4.18 Q4.3(D3) R113.2
SiPMOUT57: C103.2 J4.26 Q5.2(D2) R117.2
SiPMOUT58: C104.2 J4.19 Q4.8(D6) R121.2
SiPMOUT59: C105.2 J4.25 Q5.9(D7) R125.2
SiPMOUT60: C106.2 J4.20 Q4.4(D4) R129.2
SiPMOUT61: C107.2 J4.24 Q5.1(D1) R133.2
SiPMOUT62: C140.2 J4.21 Q4.7(D5) R137.2
SiPMOUT63: C141.2 J4.23 Q5.10(D8) R141.2
VB0: C100.2 J4.1 L1.1
VB1: C101.2 J4.2 L4.1
VB2: C102.2 J4.3 L5.1
VB3: C142.2 J4.4 L6.1
VB4: C143.2 J4.77 L7.1
VB5: C144.2 J4.78 L8.1
VB6: C145.2 J4.79 L9.1
VB7: C146.2 J4.80 L10.1
Vbias_0: J2.20 L1.2
Vbias_1: J2.19 L4.2
Vbias_2: J2.18 L5.2
Vbias_3: J2.17 L6.2
Vbias_4: J2.16 L7.2
Vbias_5: J2.15 L8.2
Vbias_6: J2.14 L9.2
Vbias_7: J2.13 L10.2
Vlogic: C34.2 C35.2 C40.2 C41.2 IC1.6(GAIN) IC1.18(VLOGIC) IC1.20(~{RESET}) IC2.6(GAIN) IC2.18(VLOGIC) IC2.20(~{RESET}) IC3.6(GAIN) IC3.18(VLOGIC) IC3.20(~{RESET}) IC4.6(GAIN) IC4.18(VLOGIC) IC4.20(~{RESET}) L2.1
Vtrim-0: C2.2 R1.1 RN6.5
Vtrim-1: C3.2 R8.1 RN3.5
Vtrim-2: C4.2 R12.1 RN5.8
Vtrim-3: C5.2 R16.1 RN4.8
Vtrim-4: C6.2 R20.1 RN6.6
Vtrim-5: C7.2 R24.1 RN3.6
Vtrim-6: C8.2 R28.1 RN5.7
Vtrim-7: C9.2 R32.1 RN4.7
Vtrim-8: C10.2 R36.1 RN6.7
Vtrim-9: C11.2 R40.1 RN3.7
Vtrim-10: C12.2 R44.1 RN5.6
Vtrim-11: C13.2 R48.1 RN4.6
Vtrim-12: C14.2 R52.1 RN6.8
Vtrim-13: C15.2 R56.1 RN3.8
Vtrim-14: C16.2 R60.1 RN5.5
Vtrim-15: C17.2 R64.1 RN4.5
Vtrim-16: C18.2 R3.1 RN8.5
Vtrim-17: C19.2 R10.1 RN1.5
Vtrim-18: C20.2 R14.1 RN7.8
Vtrim-19: C21.2 R18.1 RN2.8
Vtrim-20: C22.2 R22.1 RN8.6
Vtrim-21: C23.2 R26.1 RN1.6
Vtrim-22: C24.2 R30.1 RN7.7
Vtrim-23: C25.2 R34.1 RN2.7
Vtrim-24: C26.2 R38.1 RN8.7
Vtrim-25: C27.2 R42.1 RN1.7
Vtrim-26: C28.2 R46.1 RN7.6
Vtrim-27: C29.2 R50.1 RN2.6
Vtrim-28: C30.2 R54.1 RN8.8
Vtrim-29: C31.2 R58.1 RN1.8
Vtrim-30: C32.2 R62.1 RN7.5
Vtrim-31: C99.2 R66.1 RN2.5
Vtrim-32: C39.2 R72.1 RN15.8
Vtrim-33: C43.2 R83.1 RN14.8
Vtrim-34: C45.2 R87.1 RN16.5
Vtrim-35: C47.2 R91.1 RN13.5
Vtrim-36: C49.2 R95.1 RN15.7
Vtrim-37: C51.2 R99.1 RN14.7
Vtrim-38: C53.2 R103.1 RN16.6
Vtrim-39: C55.2 R107.1 RN13.6
Vtrim-40: C57.2 R111.1 RN15.6
Vtrim-41: C59.2 R115.1 RN14.6
Vtrim-42: C61.2 R119.1 RN16.7
Vtrim-43: C63.2 R123.1 RN13.7
Vtrim-44: C65.2 R127.1 RN15.5
Vtrim-45: C67.2 R131.1 RN14.5
Vtrim-46: C69.2 R135.1 RN16.8
Vtrim-47: C71.2 R139.1 RN13.8
Vtrim-48: C42.2 R81.1 RN17.8
Vtrim-49: C44.2 R85.1 RN10.8
Vtrim-50: C46.2 R89.1 RN18.5
Vtrim-51: C48.2 R93.1 RN9.5
Vtrim-52: C50.2 R97.1 RN17.7
Vtrim-53: C52.2 R101.1 RN10.7
Vtrim-54: C54.2 R105.1 RN18.6
Vtrim-55: C56.2 R109.1 RN9.6
Vtrim-56: C58.2 R113.1 RN17.6
Vtrim-57: C60.2 R117.1 RN10.6
Vtrim-58: C62.2 R121.1 RN18.7
Vtrim-59: C64.2 R125.1 RN9.7
Vtrim-60: C66.2 R129.1 RN17.5
Vtrim-61: C68.2 R133.1 RN10.5
Vtrim-62: C70.2 R137.1 RN18.8
Vtrim-63: C72.2 R141.1 RN9.8
N919474: IC1.19(SDO) IC2.5(SDI)
N920822: IC1.3(~{SYNC}) IC2.3(~{SYNC}) IC3.3(~{SYNC}) IC4.3(~{SYNC}) R68.1
N920826: IC1.4(SCLK) IC2.4(SCLK) IC3.4(SCLK) IC4.4(SCLK) R69.1
N920834: IC2.19(SDO) IC3.5(SDI)
N924645: IC3.19(SDO) IC4.5(SDI)
N924657: IC4.19(SDO) R71.1
N1004615: IC1.5(SDI) R70.1
N1031796: J2.12 R74.2
N1175823: IC1.14(VOUT12) RN4.1
N1175825: IC1.13(VOUT13) RN4.2
N1175827: IC1.12(VOUT14) RN4.3
N1175829: IC1.11(VOUT15) RN4.4
N1175847: IC1.25(VOUT8) RN3.1
N1175849: IC1.24(VOUT9) RN3.2
N1175851: IC1.23(VOUT10) RN3.3
N1175853: IC1.22(VOUT11) RN3.4
N1175887: IC1.10(VOUT4) RN2.1
N1175889: IC1.9(VOUT5) RN2.2
N1175891: IC1.8(VOUT6) RN2.3
N1175893: IC1.7(VOUT7) RN2.4
N1175919: IC1.1(VOUT0) RN1.1
N1175921: IC1.28(VOUT1) RN1.2
N1175923: IC1.27(VOUT2) RN1.3
N1175925: IC1.26(VOUT3) RN1.4
N1178151: IC2.25(VOUT8) RN7.1
N1178153: IC2.24(VOUT9) RN7.2
N1178155: IC2.23(VOUT10) RN7.3
N1178157: IC2.22(VOUT11) RN7.4
N1178159: IC2.10(VOUT4) RN6.1
N1178161: IC2.9(VOUT5) RN6.2
N1178163: IC2.8(VOUT6) RN6.3
N1178165: IC2.7(VOUT7) RN6.4
N1178167: IC2.14(VOUT12) RN8.1
N1178169: IC2.13(VOUT13) RN8.2
N1178171: IC2.12(VOUT14) RN8.3
N1178173: IC2.11(VOUT15) RN8.4
N1178175: IC2.1(VOUT0) RN5.1
N1178177: IC2.28(VOUT1) RN5.2
N1178179: IC2.27(VOUT2) RN5.3
N1178181: IC2.26(VOUT3) RN5.4
N1179923: IC3.10(VOUT4) RN10.1
N1179925: IC3.9(VOUT5) RN10.2
N1179927: IC3.8(VOUT6) RN10.3
N1179929: IC3.7(VOUT7) RN10.4
N1179931: IC3.14(VOUT12) RN14.1
N1179933: IC3.13(VOUT13) RN14.2
N1179935: IC3.12(VOUT14) RN14.3
N1179937: IC3.11(VOUT15) RN14.4
N1179939: IC3.1(VOUT0) RN9.1
N1179941: IC3.28(VOUT1) RN9.2
N1179943: IC3.27(VOUT2) RN9.3
N1179945: IC3.26(VOUT3) RN9.4
N1179947: IC3.25(VOUT8) RN13.1
N1179949: IC3.24(VOUT9) RN13.2
N1179951: IC3.23(VOUT10) RN13.3
N1179953: IC3.22(VOUT11) RN13.4
N1180213: IC4.14(VOUT12) RN18.1
N1180215: IC4.13(VOUT13) RN18.2
N1180217: IC4.12(VOUT14) RN18.3
N1180219: IC4.11(VOUT15) RN18.4
N1180221: IC4.1(VOUT0) RN15.1
N1180223: IC4.28(VOUT1) RN15.2
N1180225: IC4.27(VOUT2) RN15.3
N1180227: IC4.26(VOUT3) RN15.4
N1180229: IC4.25(VOUT8) RN17.1
N1180231: IC4.24(VOUT9) RN17.2
N1180233: IC4.23(VOUT10) RN17.3
N1180235: IC4.22(VOUT11) RN17.4
N1180237: IC4.10(VOUT4) RN16.1
N1180239: IC4.9(VOUT5) RN16.2
N1180241: IC4.8(VOUT6) RN16.3
N1180243: IC4.7(VOUT7) RN16.4

Not connected (* = marked no-connect by the designer): IC1 21(VREF)*; IC2 21(VREF)*; IC3 21(VREF)*; IC4 21(VREF)*; J1 41(mh1)* 42(mh2)*; J3 41(mh1)* 42(mh2)*

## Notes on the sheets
sheet 1
- To ALCOR connector mod. FLE-120-01-G-DV-A-P
sheet 2
- Novembre 2022
- Versione Adapter_Alcor_Carrier 64 canali
- Versione 64 canali Rev.2c
- Nota: Le Vbias sono 8. Connettore verso MasterLogic e' FTSH-110-01-F-D-RA 20 pins TH.
- Versione 64 canali Rev.2M
- Versione con l'aggiunta di 64 mosfet per chiudere gli ingressi a GND
  in modo da permettre l'Annealing senza scollegare la CARRIER
- Versione 64 canali Rev.2MR
- Versione con la sostituzione di 64 Resistenze 0402 con 16 resistenze SMD 4x 47ohm.
- Versione 64 canali Rev.3MR
- Aggiunti 8 condensatori di filtro delle tensioni VBias in contenitore 0402
- Le induttanze, per avere una resistenza serie inferiore, sono in case 0603
sheet 3
- The SCLK pin is continuously applied to the input shift
  register when SYNC is low. If more than 24 clock pulses
  are applied, the data ripples out of the input shift register
  and appears on the SDO line. This data is clocked out on
  the rising edge of SCLK and is valid on the falling edge. By
  connecting this line to the SDI input on the next DAC in the
  chain, a daisy-chain interface is constructed. Each DAC in
  the system requires 24 clock pulses. Therefore, the total
  number of clock cycles must equal 24 × N, where N is the
  total number of devices updated. If SYNC is brought high at
  a clock that is not a multiple of 24, it is considered a valid
  frame, and invalid data may be loaded to the DAC. When
  the serial transfer to all devices is complete, SYNC goes
  high, which latches the input data in each device in the
  daisy-chain and prevents any further data from being
  clocked into the input shift register. The serial clock can be
  continuous or a gated clock. If SYNC is held low for the
  correct number of clock cycles, a continuous SCLK source
  is used. In gated clock mode, use a burst clock containing
  the exact number of clock cycles, and bring SYNC high
  after the final clock to latch the data.
sheet 4
- From CARRIER
- 5V Power Supply, Vbias, I2C BUS, Vtrimm setting
- Connettore Samtec  SMD FTSH-110-01-F-DH-A
  oppure FTSH-110-01-L-DH-A
- To ALCOR connector mod. FLE-120-01-G-DV-A-P
